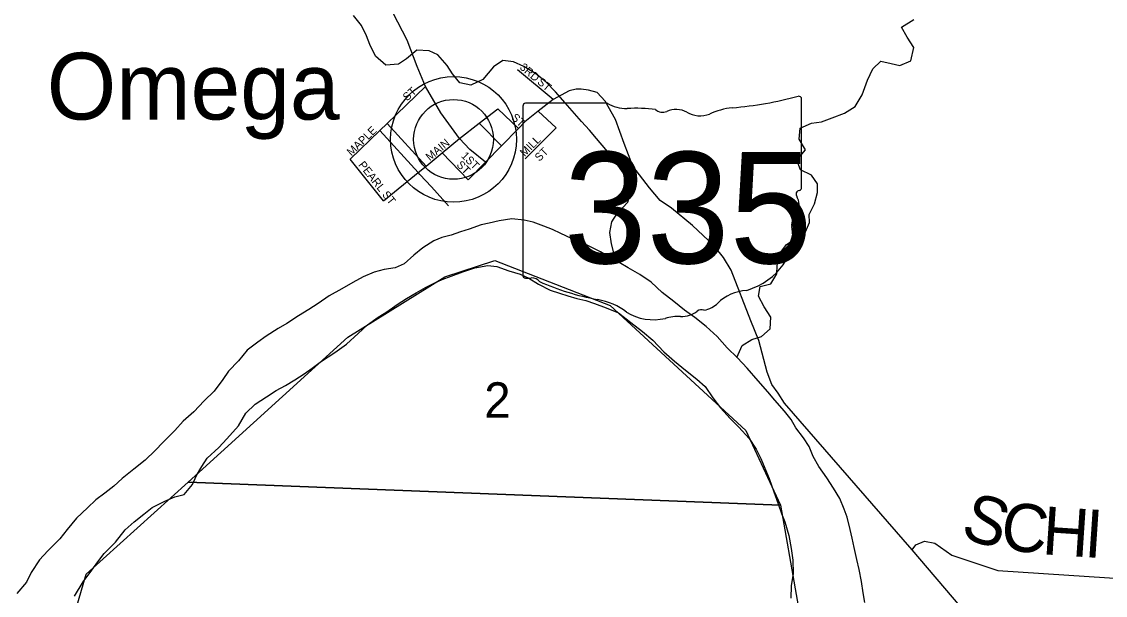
# Model space of a CAD drawing. Extents: x 0 to 34, y 0 to 22.
# Drawn here: x 26.095 to 27.377, y 18.103 to 18.782 of the extents above; entities that cross this region are included whole.
import ezdxf

# ---------------------------------------------------------------- set-up
doc = ezdxf.new("R2010")
doc.units = 0
for name, color, linetype in [('GM_X_Major_River', 7, 'Continuous'), ('GM_X_Minor_River', 7, 'Continuous'), ('GM_X_Section', 7, 'Continuous'), ('GM_X_Section_Text', 7, 'Continuous'), ('GM_X_State_Location', 7, 'Continuous'), ('GM_X_State_Route', 7, 'Continuous'), ('GM_X_State_Shield', 7, 'Continuous'), ('GM_X_Township_Road', 7, 'Continuous'), ('GM_X_Township_Road_Text', 7, 'Continuous'), ('GM_X_Township_Subdivision', 7, 'Continuous'), ('GM_X_Township_Subdivision_Text', 7, 'Continuous'), ('GM_X_Unincorporated', 7, 'Continuous'), ('GM_X_Unincorporated_Location', 7, 'Continuous'), ('GM_X_Unincorporated_Text', 7, 'Continuous')]:
    doc.layers.add(name, color=color, linetype=linetype)

msp = doc.modelspace()

# ---------------------------------------------------------------- linework, layer by layer
at = {"layer": 'GM_X_Major_River'}
for points in [[(27.0926, 18.0949), (27.0905, 18.1063), (27.0887, 18.1196), (27.0858, 18.134), (27.0829, 18.1458), (27.0797, 18.1599), (27.0775, 18.1709), (27.075, 18.1812), (27.0714, 18.1956), (27.0681, 18.2051), (27.0629, 18.2177), (27.0555, 18.2303), (27.0477, 18.2425), (27.038, 18.2559), (27.0313, 18.2677), (27.0265, 18.2795), (27.0198, 18.2895), (27.0109, 18.3017), (27.0053, 18.3112), (26.9974, 18.3212), (26.9859, 18.3342), (26.9776, 18.3441), (26.9664, 18.3572), (26.9534, 18.3721), (26.9418, 18.3844), (26.9298, 18.3962), (26.9178, 18.4097), (26.9047, 18.4216), (26.8912, 18.4319), (26.8792, 18.4408), (26.8665, 18.4512), (26.8526, 18.4616), (26.8395, 18.4739), (26.8263, 18.4831), (26.8124, 18.4908), (26.8019, 18.497), (26.7895, 18.504), (26.7797, 18.5098), (26.7586, 18.5206), (26.7455, 18.5257), (26.733, 18.5315), (26.7229, 18.5362), (26.7127, 18.5401), (26.6999, 18.5448), (26.6893, 18.5472), (26.675, 18.5489), (26.6598, 18.5464), (26.6481, 18.5439), (26.6386, 18.5417), (26.6245, 18.5365), (26.6143, 18.5333), (26.6029, 18.5296), (26.5919, 18.5267), (26.5824, 18.523), (26.5695, 18.5144), (26.5588, 18.5058), (26.5473, 18.4957), (26.537, 18.4909), (26.5238, 18.4888)], [(26.5238, 18.4888), (26.512, 18.4859), (26.4991, 18.4803), (26.4869, 18.4736), (26.4736, 18.4662), (26.4588, 18.4577), (26.4458, 18.4487), (26.4348, 18.4416), (26.4226, 18.4342), (26.4085, 18.4249), (26.3986, 18.4189), (26.3841, 18.41), (26.3742, 18.4029), (26.3616, 18.3935), (26.3513, 18.3808), (26.3398, 18.3684), (26.3329, 18.3586), (26.3225, 18.3451), (26.3107, 18.3334), (26.2988, 18.3203), (26.2862, 18.3095), (26.2763, 18.2982), (26.2625, 18.2847), (26.2529, 18.2746), (26.2411, 18.2633), (26.2277, 18.2525), (26.214, 18.2416), (26.2041, 18.2326), (26.1934, 18.224), (26.1827, 18.2162), (26.1728, 18.2068), (26.1598, 18.1945), (26.1487, 18.181), (26.1402, 18.17), (26.1261, 18.1558), (26.1161, 18.1453), (26.1061, 18.1302), (26.1007, 18.1189), (26.0892, 18.1054)], [(26.4386, 18.3722), (26.4496, 18.3804), (26.4656, 18.3905), (26.4793, 18.4006), (26.4931, 18.4133), (26.5042, 18.4234), (26.5167, 18.4324), (26.527, 18.4387), (26.5392, 18.4476), (26.5503, 18.4547), (26.5617, 18.4614), (26.5727, 18.4677), (26.583, 18.4726), (26.5925, 18.477), (26.6031, 18.4811), (26.6168, 18.4862), (26.6312, 18.491), (26.6464, 18.4935), (26.657, 18.4926), (26.6713, 18.4875), (26.6849, 18.4832), (26.695, 18.4785), (26.7063, 18.4716), (26.7202, 18.4646), (26.7311, 18.4607), (26.7413, 18.4579), (26.7519, 18.4547), (26.7624, 18.4523), (26.7726, 18.4488), (26.7866, 18.4437), (26.8009, 18.4375), (26.8155, 18.4263), (26.8294, 18.4156), (26.8418, 18.4052), (26.8545, 18.3914), (26.8672, 18.3803), (26.8803, 18.3699), (26.8938, 18.3591), (26.9036, 18.3503), (26.9125, 18.3369), (26.9218, 18.3251), (26.933, 18.3124), (26.9435, 18.3024), (26.9555, 18.289), (26.9641, 18.2761), (26.9696, 18.2654), (26.9733, 18.2559), (26.9792, 18.2414), (26.9847, 18.2258), (26.9898, 18.2117), (26.9939, 18.2003), (26.9979, 18.1904), (27.0027, 18.174), (27.0055, 18.1588), (27.0073, 18.1448), (27.0075, 18.1292), (27.0054, 18.1145), (27.0049, 18.1001)], [(26.1576, 18.1024), (26.1677, 18.1193), (26.178, 18.1332), (26.1849, 18.143), (26.1926, 18.1528), (26.206, 18.1663), (26.2175, 18.1806), (26.2282, 18.1903), (26.2393, 18.1993), (26.2492, 18.2071), (26.2644, 18.2149), (26.2762, 18.2197), (26.2872, 18.2226), (26.2971, 18.2343), (26.3018, 18.2452), (26.3083, 18.2557), (26.3145, 18.2655), (26.3282, 18.2783), (26.3378, 18.2884), (26.3516, 18.3038), (26.3601, 18.3189), (26.3711, 18.3294), (26.3845, 18.3383), (26.3959, 18.3458), (26.4069, 18.3517), (26.418, 18.3584), (26.429, 18.3655), (26.4386, 18.3722)]]:
    msp.add_lwpolyline(points, dxfattribs=at)
at = {"layer": 'GM_X_Minor_River'}
for points in [[(26.798, 18.4992), (26.7929, 18.5191), (26.7908, 18.5328), (26.7932, 18.5453), (26.7994, 18.555), (26.812, 18.5686), (26.8156, 18.5814), (26.8123, 18.591), (26.8056, 18.6043), (26.7974, 18.6165), (26.7862, 18.6311), (26.775, 18.6441), (26.7668, 18.6537), (26.7574, 18.6641), (26.7462, 18.6767), (26.738, 18.6863), (26.7267, 18.6993), (26.7151, 18.7109), (26.7027, 18.7209), (26.6892, 18.729), (26.6767, 18.7345), (26.6643, 18.7361), (26.6532, 18.7287), (26.6405, 18.7136), (26.6264, 18.707), (26.6132, 18.7098), (26.6046, 18.7205), (26.5983, 18.7304), (26.5874, 18.7431), (26.5772, 18.7478), (26.5625, 18.7483), (26.5502, 18.7382), (26.5407, 18.7319), (26.5259, 18.7309), (26.5135, 18.7413), (26.5068, 18.755), (26.5028, 18.7653), (26.4969, 18.7775), (26.4875, 18.7894)], [(26.9412, 18.3849), (26.9473, 18.3989), (26.9587, 18.4059), (26.9701, 18.4096), (26.9805, 18.4186), (26.9814, 18.4323), (26.9732, 18.4449), (26.9665, 18.4575), (26.9685, 18.4688), (26.9811, 18.4721), (26.9884, 18.4838), (26.9889, 18.4933), (26.9909, 18.5061), (26.9998, 18.5186), (27.012, 18.5264), (27.0223, 18.5335), (27.027, 18.5444), (27.0267, 18.5539), (27.0329, 18.5668), (27.0365, 18.58), (27.0366, 18.5903), (27.0292, 18.6006), (27.0163, 18.6068), (27.0119, 18.6182), (27.0223, 18.6306), (27.0149, 18.6433), (27.0161, 18.6561), (27.0295, 18.6621), (27.0412, 18.6638), (27.0538, 18.6682), (27.0686, 18.6738), (27.0812, 18.682), (27.0894, 18.6955), (27.0956, 18.7129), (27.1018, 18.7265), (27.1114, 18.7355), (27.1235, 18.7327), (27.1337, 18.7303), (27.1467, 18.7359), (27.1503, 18.7518), (27.1424, 18.764), (27.1358, 18.7758), (27.1503, 18.7848)]]:
    msp.add_lwpolyline(points, dxfattribs=at)
at = {"layer": 'GM_X_Section'}
for points in [[(26.2918, 18.2374), (26.4809, 18.4089), (26.5956, 18.4803), (26.6548, 18.4997), (26.7913, 18.4464), (26.9516, 18.2983), (26.9928, 18.2098)], [(26.2918, 18.2374), (26.9928, 18.2098), (27.0297, 17.9987), (27.1053, 17.8104), (27.0604, 17.2208), (26.2538, 17.2713), (26.2518, 17.5615), (26.1636, 17.7312), (26.1119, 17.9239), (26.1712, 18.1282)]]:
    msp.add_lwpolyline(points, close=True, dxfattribs=at)
at = {"layer": 'GM_X_State_Route'}
for points in [[(27.0638, 18.2546), (26.9976, 18.3308), (26.99, 18.3425), (26.9824, 18.3527), (26.977, 18.3675), (26.967, 18.4047), (26.9575, 18.4282), (26.9345, 18.4882), (26.9254, 18.503), (26.914, 18.5174), (26.8885, 18.5409), (26.8637, 18.5613), (26.8504, 18.5704), (26.8378, 18.5855), (26.818, 18.6113), (26.8077, 18.6382), (26.7974, 18.6663), (26.7852, 18.6883), (26.776, 18.6982), (26.7654, 18.7012), (26.757, 18.7023), (26.7509, 18.7023), (26.7426, 18.7003), (26.7236, 18.6899), (26.7062, 18.6764), (26.6903, 18.6637), (26.6826, 18.6558), (26.6626, 18.6352), (26.6438, 18.6158), (26.6251, 18.6309), (26.613, 18.6438), (26.5908, 18.6745), (26.5726, 18.7055), (26.563, 18.7291), (26.5511, 18.7602), (26.5343, 18.7924)], [(27.0589, 17.5054), (27.0574, 17.5148), (27.0557, 17.5501), (27.0594, 17.5908), (27.0711, 17.6227), (27.0873, 17.652), (27.0987, 17.6676), (27.2718, 17.9028), (27.2801, 17.9184), (27.2862, 17.9347), (27.2903, 17.9514), (27.2864, 17.981), (27.2772, 18.0008), (27.262, 18.0239), (27.1485, 18.1572), (27.0638, 18.2546)]]:
    msp.add_lwpolyline(points, dxfattribs=at)
at = {"layer": 'GM_X_State_Shield'}
for p, q in [((26.688, 18.6822), (26.688, 18.4821)), ((26.7878, 18.6856), (26.6912, 18.6856)), ((27.0176, 18.5859), (27.0176, 18.6906)), ((27.0175, 18.5859), (27.0176, 18.5859))]:
    msp.add_line(p, q, dxfattribs=at)
for centre, major_axis, start_param, end_param in [((26.9002, 18.9585), (0.3495, 0), 4.814394, 5.042369), ((27.0139, 18.691), (0.00367, 0), 6.141152, 7.989035), ((26.6918, 18.6826), (0.00382, 0), 1.712693, 3.28349), ((26.8107, 18.7089), (0.037, 0), 4.042523, 4.731795), ((26.823, 18.5733), (0.133, 0), 1.404758, 1.657858), ((26.8689, 18.6605), (0.0222, 0), 0.950623, 2.079405), ((26.9447, 18.6245), (0.0703, 0), 1.699011, 2.107814), ((26.8532, 18.6836), (0.0107, 0), 3.836095, 5.185415), ((26.8976, 18.6922), (0.0267, 0), 4.081561, 5.145723), ((27.0167, 18.5782), (0.00568, 0), 1.883978, 3.671073), ((27.0137, 18.5855), (0.00393, 0), 5.05454, 6.418171), ((26.9806, 18.565), (0.0341, 0), 5.934695, 6.695948), ((27.0307, 18.5421), (0.0248, 0), 2.387724, 3.262537), ((26.9197, 18.5288), (0.0874, 0), 5.101752, 6.440018), ((26.6918, 18.4816), (0.00385, 0), 3.00124, 4.508301), ((26.6924, 18.5021), (0.0294, 0), 4.665946, 4.897461), ((26.6984, 18.4705), (0.0106, 0), 0.519207, 1.627899), ((26.8322, 18.6503), (0.2524, 0), 4.195997, 4.488961), ((26.9566, 18.4259), (0.0479, 0), 1.647645, 2.488434), ((26.757, 18.3922), (0.079, 0), 0.823519, 1.323587), ((26.8959, 18.4627), (0.0282, 0), 4.937069, 5.64225), ((26.8424, 18.4695), (0.0501, 0), 4.026481, 4.996735), ((26.875, 18.4545), (0.0267, 0), 4.691044, 5.507374), ((26.8992, 18.4352), (0.00752, 0), 1.147584, 2.315152), ((26.8713, 18.4003), (0.0412, 0), 1.495662, 1.94098)]:
    msp.add_ellipse(centre, major_axis=major_axis, ratio=0.8, start_param=start_param, end_param=end_param, dxfattribs=at)
at = {"layer": 'GM_X_Township_Road'}
msp.add_lwpolyline([(27.1485, 18.1572), (27.153, 18.1629), (27.1629, 18.1674), (27.1753, 18.1651), (27.1953, 18.1509), (27.2498, 18.1328), (27.436, 18.1203), (27.6307, 18.1188), (27.944, 18.1227), (27.9625, 18.1237), (27.9982, 18.1364), (28.4629, 18.4537), (28.5488, 18.5052), (28.6466, 18.5805), (28.777, 18.6591), (28.8222, 18.6888), (28.8454, 18.7016), (28.8686, 18.7105), (28.8906, 18.7294), (28.9056, 18.7513), (28.9087, 18.7665), (28.9065, 18.7786)], dxfattribs=at)
at = {"layer": 'GM_X_Township_Subdivision'}
for points in [[(26.7236, 18.6899), (26.6814, 18.7252)], [(26.4837, 18.6194), (26.5188, 18.6534), (26.5274, 18.6617), (26.5726, 18.7055)], [(26.613, 18.6438), (26.6362, 18.6619), (26.6581, 18.679), (26.6826, 18.6558)], [(26.6905, 18.6198), (26.7274, 18.6565), (26.7062, 18.6764)], [(26.5734, 18.6113), (26.5274, 18.6617)], [(26.6626, 18.6352), (26.6362, 18.6619)], [(26.5661, 18.6015), (26.5641, 18.6037), (26.5188, 18.6534)], [(26.5231, 18.57), (26.5641, 18.6037), (26.5734, 18.6113), (26.5923, 18.6268), (26.613, 18.6438)], [(26.5231, 18.57), (26.4837, 18.6194)], [(26.6231, 18.5949), (26.5923, 18.6268)], [(26.6231, 18.5949), (26.6438, 18.6158)], [(26.5797, 18.5866), (26.5661, 18.6015), (26.5661, 18.6015)], [(26.5999, 18.5644), (26.5797, 18.5866), (26.5797, 18.5866)]]:
    msp.add_lwpolyline(points, dxfattribs=at)
at = {"layer": 'GM_X_Unincorporated'}
for radius in [0.0744, 0.0472]:
    msp.add_circle((26.6059, 18.6429), radius, dxfattribs=at)
at = {"layer": 'GM_X_Unincorporated_Location'}
msp.add_line((26.6059, 18.6429), (26.6059, 18.6429), dxfattribs=at)

# ---------------------------------------------------------------- texts
at = {"layer": 'GM_X_Section_Text'}
msp.add_text('2', height=0.0419, rotation=0, dxfattribs=at).set_placement((26.6422, 18.3135))
at = {"layer": 'GM_X_State_Location'}
for s in ['s', 'r']:
    msp.add_text(s, height=0.000189, dxfattribs=at).set_placement((26.8491, 18.5688))
msp.add_text('335', height=0.000189, rotation=0, dxfattribs=at).set_placement((26.7822, 18.555))
at = {"layer": 'GM_X_State_Shield'}
msp.add_text('335', height=0.13184, dxfattribs=at).set_placement((26.7363, 18.4962))
at = {"layer": 'GM_X_Township_Road_Text'}
for s, rotation, p in [('S', 342.4952, (27.204, 18.1724)), ('C', 352.4367, (27.2511, 18.1586)), ('H', 356.1717, (27.3013, 18.152)), ('I', 356.1724, (27.3512, 18.1487))]:
    msp.add_text(s, height=0.0568, rotation=rotation, dxfattribs=at).set_placement(p)
at = {"layer": 'GM_X_Township_Subdivision_Text'}
for s, rotation, p in [('3RD', 319.6272, (26.6834, 18.7269)), ('ST', 42.5022, (26.551, 18.6877)), ('ST', 320.1908, (26.7042, 18.7095)), ('ST', 317.4978, (26.6734, 18.6677)), ('MAPLE', 44.1421, (26.4851, 18.6227)), ('MAIN', 39.611, (26.5778, 18.617)), ('MILL', 44.9954, (26.6901, 18.6218)), ('ST', 44.9909, (26.7075, 18.6162)), ('PEARL ST', 308.5154, (26.4928, 18.6125)), ('ST', 315, (26.6087, 18.6121)), ('1ST', 315, (26.6142, 18.6226))]:
    msp.add_text(s, height=0.00947, rotation=rotation, dxfattribs=at).set_placement(p)
at = {"layer": 'GM_X_Unincorporated_Text'}
msp.add_text('Omega', height=0.07898, rotation=0, dxfattribs=at).set_placement((26.1247, 18.6664))

doc.saveas('drawing.dxf')
